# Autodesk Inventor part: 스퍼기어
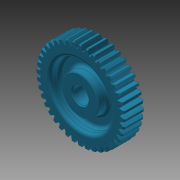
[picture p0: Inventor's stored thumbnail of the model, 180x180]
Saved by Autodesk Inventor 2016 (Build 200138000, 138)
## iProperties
Created: 2018-11
Part Number: 스퍼기어
Material: 알루미늄 6061
Document SubType Name: Modeling
Designer: mduedu
Categories: <?xml version="1.0" encoding="UTF-16"?> <MemberInstance><Categories><FamilyTemplate><FamilyTemplateParameter ValueType="xs:double" Id="1" ObjectReferenceKey="da
Density: 1 g/cm^3
Appearance: 터키옥색
CustomPartVersion: 1
Author: mduedu
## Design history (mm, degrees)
sketch "Sketch1"
  geometry: C1 r 42 at (0, 0)
  constraints: 1 centre point
  dimensions: "d0" = 83.99905 diameter of C1 (= da_da)
extrude "Extrusion1" new body sketch "Sketch1" distance "d1" = 19 (= da_b); taper "d2" = 0 deg
workplane "Work Plane2"
sketch "Sketch2"
  geometry: C1 r 42 at (0, 0) reference; C2 r 40.05 at (0, 0)
  constraints: 1 centre point, 1 coincident
  dimensions: "d3" = 80.10038 diameter of C2 (= da_dw)
feature "피치 지름" sketch "Sketch2" dims "d4" = 10, "d5" = 0
workplane "Work Plane8"
workplane "Work Plane9"
feature "스퍼 기어" dims "da_b" = 19, "da_d" = 80, "da_aw" = 80.10038, "da_da" = 83.99905, "da_df" = 75, "da_dw" = 80.10038, angle "da_beta" = 0 deg, "da_lefttooth" = 0, "da_righttooth" = 0
sketch "스케치3"
  geometry: L1 (-42, 19)-(42, 19) reference; L2 (42, 19)-(42, 0) reference; L3 (42, 0)-(-42, 0) reference; L4 (-42, 0)-(-42, 19) reference; L5 (0, 0)-(0, 19); L6 (42, 0)-(41, 0); L7 (42, 1)-(42, 0); L8 (42, 19)-(41, 19); L9 (42, 18)-(42, 19); L10 (41, 19)-(42, 18); L11 (41, 0)-(42, 1)
  constraints: 14 end point, 2 horizontal, 2 vertical, 1 midpoint
  dimensions: "d49" = 1 distance from line of L8.end L2; "d50" = 1 horizontal distance of L8.end L9.start; "d51" = 1 horizontal distance of L6.end L7.start; "d52" = 1 horizontal distance of L6.end L7.start
revolve "회전1" sketch "스케치3" stored, may be unused: angle "d53" = 90 deg
sketch "스케치4"
  geometry: L1 (-2.5, 7.071)-(2.5, 7.071); L2 (2.5, 7.071)-(2.5, 9.8); L3 (2.5, 9.8)-(-2.5, 9.8); L4 (-2.5, 9.8)-(-2.5, 7.071); A1 r 7.5 centre (0, 0) between (-2.5, 7.071) and (2.5, 7.071); 1 further point
  constraints: 8 end point, 2 parallel, 2 point on circle, 1 centre point, 1 coincident, 1 horizontal, 1 perpendicular
  dimensions: "d54" = 15 diameter of A1; "d56" = 17.3 dimension on A1 L3; "d57" = 5 distance of L2.end L3.end
extrude "돌출2" cut sketch "스케치4" stored distance "d58" = 10; taper "d59" = 0 deg
chamfer "모따기1" distance "d60" = 1; stored, may be unused: second distance "d61" = 2, angle "d62" = 45 deg
sketch "스케치5"
  geometry: C1 r 17.5 at (0, 0); C2 r 28.5 at (0, 0); 1 further point
  constraints: 2 centre point, 2 coincident
  dimensions: "d63" = 35 diameter of C1; "d64" = 57 diameter of C2
extrude "돌출3" cut sketch "스케치5" distance "d65" = 9.5; taper "d66" = 0 deg
fillet "모깎기1" dims "d67" = 3
chamfer "모따기2" distance "d68" = 0.5; stored, may be unused: second distance "d69" = 2, angle "d70" = 45 deg
body "Solid1"
body "Srf1"
node "절단 모서리 투영1"
other parameters: "d16" = 80.10038 (= da_aw), "d17" = 0, "d34" = 4.5 deg (computed from da_z), "d39" = 0, "d41" = 0, "d43" = 80.10038 (= da_aw), "d46" = 80.10038 (= da_aw), "d47" = 0, "d48" = 0
